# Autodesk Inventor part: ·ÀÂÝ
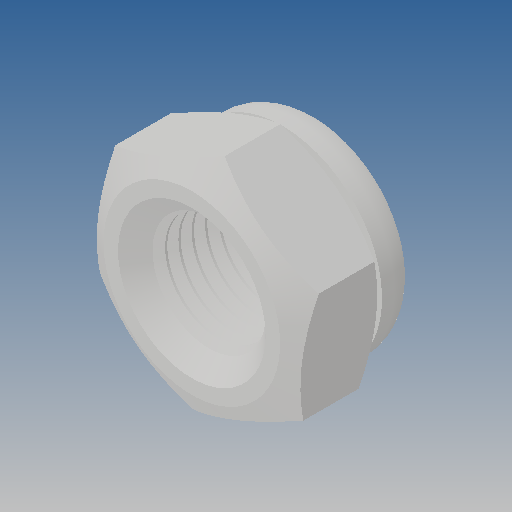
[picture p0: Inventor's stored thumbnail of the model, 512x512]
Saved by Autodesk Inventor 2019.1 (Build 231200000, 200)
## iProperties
Created: 2017-10
Part Number: ·ÀÂÝ
Material: Ogólny
Document SubType Name: Modeling
Designer: CADENGINEERING4
Density: 1 g/cm^3
Appearance: Domyślna
Author: CADENGINEERING4
Revision Number: ÈÎºÎ
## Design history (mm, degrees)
feature "prevailing torque type style 1 gb-2-solid1"
node "Bryła1"
